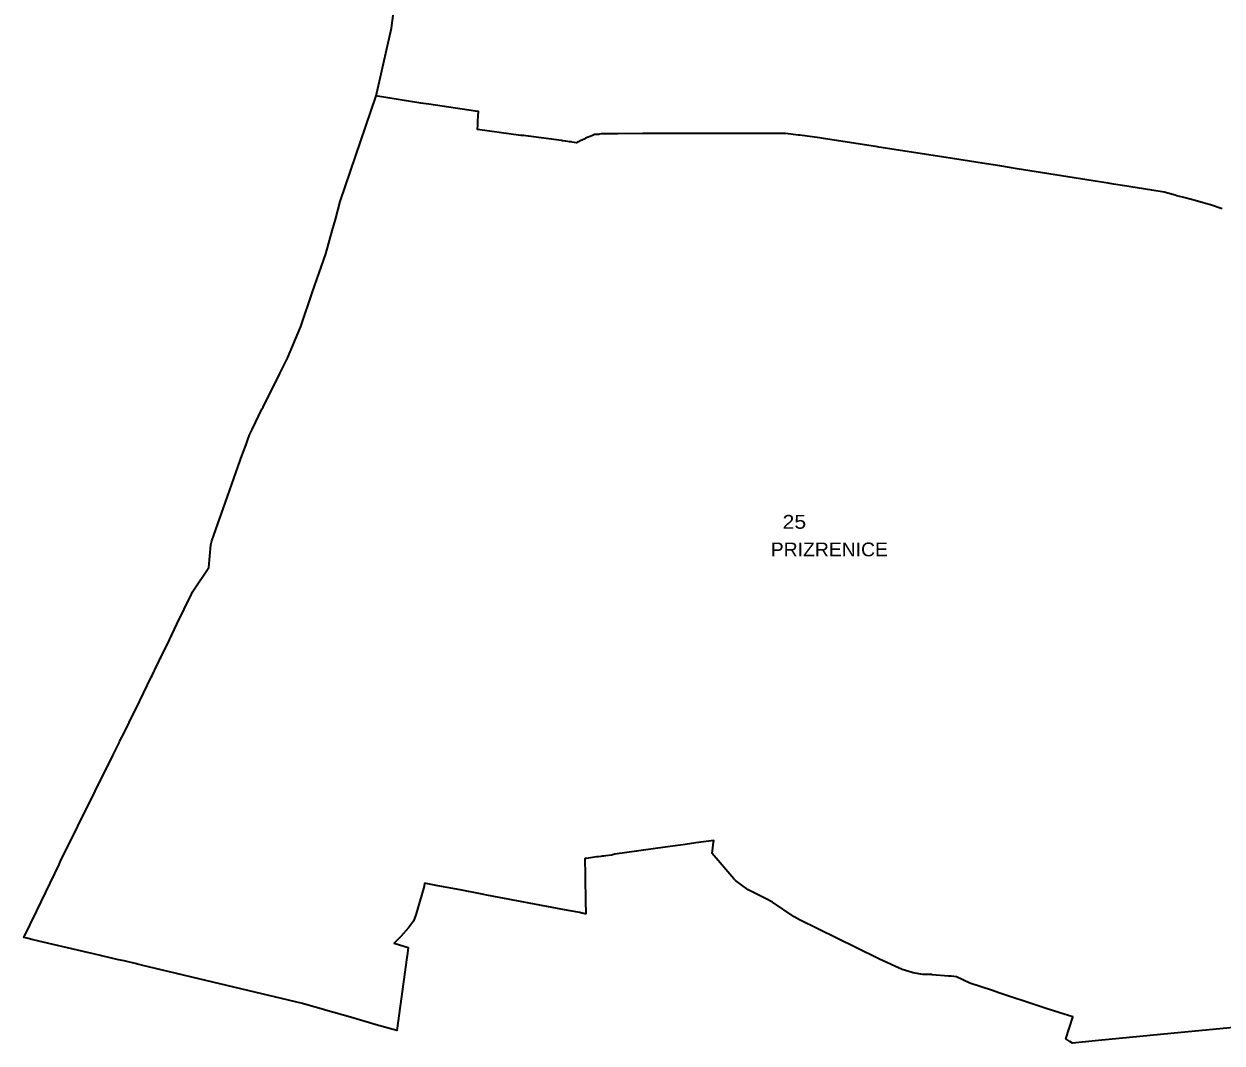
# Model space of a CAD drawing. Extents: x -610940 to -588976, y -1170376 to -1149800.
# Drawn here: x -600200 to -598026, y -1167354 to -1165505 of the extents above; entities that cross this region are included whole.
import ezdxf

# ---------------------------------------------------------------- set-up
doc = ezdxf.new("R2010")
doc.units = 0
doc.header["$LTSCALE"] = 10
doc.layers.add('54', color=7, linetype='Continuous', lineweight=35)
doc.layers.add('55', color=7, linetype='Continuous')
doc.layers.add('56', color=7, linetype='Continuous')

msp = doc.modelspace()

# ---------------------------------------------------------------- linework, layer by layer
at = {"layer": '54'}
for points in [[(-599561.21, -1165635.45), (-599533.24, -1165513.01), (-599527.85, -1165471.2), (-599522.9, -1165429.45), (-599520.56, -1165411.26)], [(-599997.19, -1166748.31), (-599969.01, -1166690.56), (-599967.46, -1166687.13), (-599958.09, -1166667.83), (-599957.91, -1166667.27), (-599952.61, -1166656.49), (-599951, -1166653.17), (-599936.08, -1166622.47), (-599922.44, -1166594.03), (-599896.17, -1166539.65), (-599894.11, -1166535.38), (-599864.8, -1166491.22), (-599860.72, -1166450.11), (-599859, -1166443.11), (-599830.65, -1166362.52), (-599807.44, -1166297.39), (-599806.23, -1166293.89), (-599796.8, -1166267.98), (-599794.93, -1166262.86), (-599790.63, -1166250.47), (-599790.5, -1166250.1), (-599789.84, -1166248.83), (-599789.48, -1166248.12), (-599786.98, -1166243.27), (-599785.86, -1166241.07), (-599785.7, -1166240.75), (-599768.3, -1166204.38), (-599766.17, -1166200.21), (-599735.92, -1166139.64), (-599721.77, -1166111.39), (-599697.88, -1166054.04), (-599676.32, -1165991), (-599652.39, -1165922.23), (-599641, -1165880.62), (-599635.01, -1165859.94), (-599626.07, -1165827.19), (-599561.21, -1165635.45)], [(-599298.27, -1165707.28), (-599377.01, -1165696.73), (-599376.6, -1165687.92), (-599376.54, -1165686.69), (-599376.22, -1165679.81), (-599375.92, -1165673.54), (-599375.86, -1165672.16), (-599375.48, -1165664.01), (-599381.03, -1165663.18), (-599465.34, -1165650.51), (-599479.9, -1165649.02), (-599558.35, -1165635.9), (-599559.2, -1165635.77), (-599561.21, -1165635.45)], [(-598863.43, -1165703.65), (-598955.39, -1165704.17), (-598956.15, -1165704.17), (-598966.13, -1165704.22), (-598972.54, -1165704.21), (-599077.08, -1165704.02), (-599122.64, -1165704.24), (-599133.87, -1165704.3), (-599152.96, -1165704.47), (-599155.66, -1165705.44), (-599156.64, -1165705.47), (-599157.39, -1165705.49), (-599164.55, -1165705.69), (-599165.93, -1165706.32), (-599169.52, -1165707.97), (-599180.97, -1165712.63), (-599183.86, -1165713.96), (-599185.75, -1165714.82), (-599187.76, -1165715.75), (-599189.74, -1165716.66), (-599190.38, -1165716.95), (-599191.18, -1165717.38), (-599193.95, -1165718.85), (-599194.73, -1165719.26), (-599195.39, -1165719.61), (-599197.53, -1165720.67), (-599205.94, -1165719.44), (-599206.66, -1165719.34), (-599208.89, -1165719.01), (-599209.66, -1165718.91), (-599210.37, -1165718.82), (-599216.64, -1165717.98), (-599217.32, -1165717.89), (-599222.91, -1165717.14), (-599224.51, -1165716.8), (-599284.37, -1165708.82), (-599285.25, -1165708.71), (-599289.49, -1165708.21), (-599292.86, -1165707.85), (-599298.27, -1165707.28)], [(-598025.88, -1165840.66), (-598047.21, -1165833.64), (-598056.16, -1165830.69), (-598060.55, -1165829.52), (-598075.26, -1165825.61), (-598093.32, -1165820.8), (-598108.1, -1165816.87), (-598111.1, -1165816.03), (-598131.31, -1165810.3), (-598153.77, -1165806.7), (-598180.27, -1165802.44), (-598206.65, -1165798.2), (-598223.01, -1165795.57), (-598233.08, -1165793.95), (-598248.64, -1165791.47), (-598397.93, -1165767.77), (-598429.37, -1165762.6), (-598461.79, -1165757.57), (-598526.61, -1165747.51), (-598649.11, -1165728.47), (-598651.14, -1165728.16), (-598749.64, -1165712.86), (-598756.42, -1165711.59), (-598792.29, -1165707.15), (-598794.84, -1165706.76), (-598818.02, -1165704.13), (-598818.59, -1165704.13), (-598830.56, -1165704), (-598858.08, -1165703.71), (-598863.43, -1165703.65)], [(-599473.49, -1167064.11), (-599474.14, -1167069.32), (-599478.86, -1167086.77), (-599481.82, -1167096.56), (-599488.89, -1167121.73), (-599493.16, -1167133.11), (-599502.21, -1167144.98), (-599516.46, -1167160.69), (-599528.18, -1167173.18), (-599502.9, -1167180.93), (-599504.69, -1167195.74), (-599505.17, -1167199.21), (-599523.17, -1167331.7), (-599560.91, -1167320.9), (-599607.65, -1167307.54), (-599652.71, -1167294.65), (-599654.51, -1167294.13), (-599694.75, -1167282.44), (-599806.69, -1167255.91), (-599844.58, -1167246.71), (-599961.36, -1167218.82), (-599986.94, -1167212.76), (-599991.69, -1167211.63), (-599998.2, -1167210.1), (-600017.86, -1167205.33), (-600028.52, -1167202.96), (-600074.01, -1167192.27), (-600084.54, -1167189.68), (-600183.01, -1167166.86), (-600194.85, -1167164.02), (-600199.94, -1167162.83), (-600176.53, -1167114.14), (-600136.3, -1167030.13), (-600134.05, -1167025.57), (-600038.67, -1166832.22), (-600027.46, -1166809.49), (-600026.38, -1166807.32), (-600018.44, -1166791.26), (-599999.98, -1166753.94), (-599997.19, -1166748.31)], [(-598606.79, -1167221.05), (-598647.8, -1167201.79), (-598651.65, -1167199.98), (-598725.46, -1167163.7), (-598792.69, -1167130.92), (-598802.58, -1167125.07), (-598841.87, -1167098.39), (-598855.94, -1167091.17), (-598871.29, -1167083.51), (-598885.76, -1167076.28), (-598909.24, -1167059.29), (-598911.84, -1167056.47), (-598951.62, -1167010.02), (-598948.84, -1166989.66), (-598948.51, -1166986.92), (-598980.91, -1166990.99), (-599000.38, -1166993.8), (-599036.7, -1166998.8), (-599127.68, -1167011.78), (-599134.13, -1167013.03), (-599144.14, -1167014.38), (-599148.03, -1167014.91), (-599150.8, -1167015.28), (-599153.36, -1167015.63), (-599158.15, -1167016.28), (-599160.92, -1167016.64), (-599164.71, -1167017.14), (-599175.6, -1167018.58), (-599179.42, -1167019.24), (-599181.04, -1167019.52), (-599182.2, -1167019.72), (-599181.62, -1167049), (-599181.55, -1167054.18), (-599181.05, -1167095.89), (-599180.51, -1167119.9), (-599182.47, -1167119.49), (-599184.47, -1167119.07), (-599186.41, -1167118.67), (-599187.9, -1167118.35), (-599191.42, -1167117.62)], [(-599191.42, -1167117.62), (-599195.36, -1167116.79), (-599218.99, -1167112.37), (-599360.4, -1167085.95), (-599368.9, -1167084.14), (-599408.52, -1167076.37), (-599448.84, -1167068.94), (-599473.49, -1167064.11)], [(-598004.63, -1167326.28), (-598100.53, -1167335.31), (-598250.58, -1167349.5), (-598297.75, -1167354.19), (-598302.5, -1167351.13), (-598307.95, -1167347.61), (-598309.99, -1167346.3), (-598297.06, -1167307.18), (-598296.96, -1167306.9), (-598320.63, -1167299.12), (-598345.43, -1167291.27), (-598357.96, -1167286.99), (-598431.55, -1167262.86), (-598442.72, -1167258.9), (-598484.07, -1167245.34), (-598507.88, -1167233.8), (-598517.88, -1167233.1), (-598522.69, -1167232.68), (-598552.12, -1167230.16), (-598553.19, -1167230.13), (-598569.32, -1167229.54), (-598586.92, -1167226.81), (-598588.44, -1167226.37), (-598606.79, -1167221.05)]]:
    msp.add_lwpolyline(points, dxfattribs=at)

# ---------------------------------------------------------------- texts
at = {"layer": '55', "width": 1.05}
msp.add_text('PRIZRENICE ', height=25, dxfattribs=at).set_placement((-598845.01, -1166471.09))
at = {"layer": '56', "width": 1.15}
msp.add_text('25 ', height=25, dxfattribs=at).set_placement((-598823.63, -1166421.06))

doc.saveas('drawing.dxf')
